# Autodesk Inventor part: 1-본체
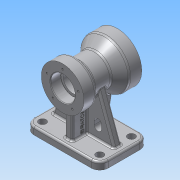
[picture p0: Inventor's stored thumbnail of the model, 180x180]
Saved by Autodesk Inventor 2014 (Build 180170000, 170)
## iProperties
Created: 2015-08
Part Number: 1-본체
Material: 알루미늄 6061
Document SubType Name: Modeling
Designer: SDA16
Density: 2.71 g/cm^3
Appearance: 알루미늄 - 평지
Author: SDA16
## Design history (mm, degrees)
sketch "스케치1"
  geometry: L1 (61, -40)-(-61, -40); L2 (-61, -40)-(-61, 40); L3 (-61, 40)-(61, 40); L4 (61, 40)-(61, -40); L5 (61, -40)-(-61, 40); L6 (-61, -40)-(61, 40); 1 further point
  constraints: 12 end point, 2 midpoint, 2 parallel, 1 horizontal, 1 perpendicular
  dimensions: "d0" = 122 distance of L1.start L1.end; "d1" = 80 distance of L3.end L1.start
extrude "돌출1" new body sketch "스케치1" distance "d2" = 12; taper "d3" = 0 deg
sketch "스케치2"
  geometry: L1 (-40, 0)-(-40, 12) reference; L2 (40, 0)-(-40, 0) reference; L3 (-40, 90)-(50, 90); L4 (-40, 90)-(-40, 125); L5 (-40, 125)-(-20, 125); L6 (-20, 125)-(-14.804, 116); L7 (-14.804, 116)-(13.315, 116); L8 (13.315, 116)-(30, 130); L9 (30, 130)-(50, 130); L10 (50, 130)-(50, 90); 1 further point
  constraints: 16 end point, 4 parallel, 2 perpendicular, 1 vertical alignment
  dimensions: "d4" = 90 distance of L3.start L3.end; "d5" = 90 distance between parallel lines of L2 L3; "d6" = 20 distance of L4.end L5.end; "d7" = 20 distance of L8.end L9.end; "d8" = 60 deg angle of L7 L6; "d9" = 40 deg angle of L8 L7; "d10" = 70 diameter of L5 L3; "d11" = 80 diameter of L9 L3; "d12" = 52 diameter of L7 L3
revolve "회전1" sketch "스케치2" stored, may be unused: angle "d13" = 90 deg
sketch "스케치3"
  geometry: L1 (-61, 12)-(61, 12) reference; L2 (-21.331, 93.514)-(-51, 12); L3 (51, 12)-(21.331, 93.514); L4 (21.331, 93.514)-(-21.331, 93.514); L5 (61, 0)-(-61, 0) reference; L6 (61, 0)-(61, 12) reference; 3 further points
  constraints: 6 end point, 2 midpoint, 2 point on line, 1 equal length, 1 parallel, 1 vertical alignment
  dimensions: "d14" = 70 deg angle of L1 L3; "d15" = 10 distance from line of L3.start L6; "d16" = 42.66233 distance of L3.end L2.start
extrude "돌출2" join sketch "스케치3" stored distance "d17" = 12; taper "d18" = 0 deg
sketch "스케치4"
  geometry: L1 (-40, 12)-(40, 12) reference; L2 (-30, 12)-(-30, 98.4); L3 (-30, 98.4)-(38.921, 98.4); L4 (38.921, 98.4)-(38.921, 62.592); L5 (38.921, 62.592)-(30, 12); L6 (-40, 0)-(-40, 12) reference; 1 further point
  constraints: 8 end point, 2 perpendicular, 2 point on line, 1 parallel
  dimensions: "d19" = 80 deg angle of L1 L5; "d20" = 10 distance of L5.end L1.end; "d21" = 10 distance between parallel lines of L2 L6; "d22" = 68.92069 distance of L2.end L3.end; "d23" = 35.80857 distance of L3.end L4.end
extrude "돌출3" join sketch "스케치4" stored distance "d24" = 12; taper "d25" = 0 deg
hole "구멍1" diameter "d28" = 38; stored, may be unused: countersink angle "d32" = 90 deg, drill point angle "d34" = 0 deg; dims "d29" = 6, "d30" = 52, "d31" = 20, "d33" = 23, "d35" = 10, "d36" = 10
hole "구멍2" diameter "d39" = 32; stored, may be unused: countersink angle "d43" = 90 deg, drill point angle "d45" = 0 deg; dims "d37" = 10, "d38" = 10, "d40" = 6, "d41" = 40, "d42" = 17, "d44" = 23
sketch "스케치5"
  geometry: C1 r 26 at (0, 0) reference; 2 further points
  constraints: 1 vertical alignment
  dimensions: "d47" = 33 distance of point (0, -33) C1.centre
hole "구멍3" sketch "스케치5" at (0, -33) diameter "d48" = 3.242; stored, may be unused: countersink angle "d52" = 90 deg, drill point angle "d54" = 118 deg; dims "d49" = 10, "d50" = 40, "d51" = 17, "d53" = 13
sketch "스케치6"
  geometry: C1 r 20 at (0, 0) reference; 2 further points
  constraints: 1 vertical alignment
  dimensions: "d58" = 27 distance of C1.centre point (0, 27)
hole "구멍4" sketch "스케치6" at (0, 27) diameter "d59" = 3.242; stored, may be unused: countersink angle "d63" = 90 deg, drill point angle "d65" = 118 deg; dims "d60" = 10, "d61" = 40, "d62" = 17, "d64" = 13
sketch "스케치7"
  geometry: L1 (-6, 12)-(-51, 12) reference; L2 (-30, 36)-(-30, 30); L3 (-18, 30)-(-18, 36); L4 (18, 36)-(18, 30); L5 (30, 30)-(30, 36); L6 (-61, 12)-(61, 12) reference; A1 r 6 centre (-24, 30) between (-30, 30) and (-18, 30); A2 r 6 centre (-24, 36) between (-18, 36) and (-30, 36); A3 r 6 centre (24, 30) between (18, 30) and (30, 30); A4 r 6 centre (24, 36) between (30, 36) and (18, 36); 2 further points
  constraints: 8 end point, 8 point on circle, 8 tangent, 4 centre point, 4 parallel, 2 horizontal alignment, 1 coincident, 1 equal radius, 1 perpendicular
  dimensions: "d69" = 48 distance of A3.centre A1.centre; "d70" = 18 distance from line of L1 A1.centre; "d72" = 12 distance between parallel lines of L3 L2; "d73" = 24 horizontal distance of point (0, 0) A1.centre; "d76" = 6 distance of A1.centre A2.centre
extrude "돌출4" cut sketch "스케치7" stored distance "d74" = 12; taper "d75" = 0 deg
sketch "스케치8"
  geometry: L1 (47, -26)-(-47, -26); L2 (-47, -26)-(-47, 26); L3 (-47, 26)-(47, 26); L4 (47, 26)-(47, -26); L5 (47, -26)-(-47, 26); L6 (-47, -26)-(47, 26); 5 further points
  constraints: 12 end point, 4 coincident, 2 midpoint, 2 parallel, 1 horizontal, 1 perpendicular
  dimensions: "d77" = 94 distance of L2.end L3.end; "d78" = 52 distance of L3.end L1.start
hole "구멍5" sketch "스케치8" at (-47, 26), (-47, -26), (47, -26), (47, 26) diameter "d79" = 12; stored, may be unused: countersink angle "d83" = 90 deg, drill point angle "d85" = 0 deg; dims "d80" = 12, "d81" = 40, "d82" = 17, "d84" = 13
sketch "스케치9"
  geometry: L1 (-55.518, -30)-(-12, -30) reference; L2 (-12, -6)-(-12, -30) reference; 2 further points
  constraints: 1 other
  dimensions: "d86" = 16 distance from line of point (-36, -14) L1; "d87" = 24 distance from line of point (-36, -14) L2
feature "엠보싱1" sketch "스케치9" dims "d88" = 0.5, "d89" = 0
fillet "모깎기1" dims "d90" = 5, "d91" = 0.3, "d92" = 14
fillet "모깎기2" dims "d93" = 3
fillet "모깎기3" dims "d94" = 3
chamfer "모따기1" distance "d95" = 1; stored, may be unused: second distance "d96" = 2, angle "d97" = 45 deg
node "솔리드1"
pattern_circular "원형 패턴1" dims angle "d56" = 360 deg
pattern_circular "원형 패턴2" dims angle "d67" = 360 deg
